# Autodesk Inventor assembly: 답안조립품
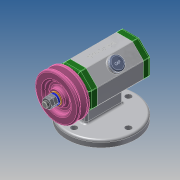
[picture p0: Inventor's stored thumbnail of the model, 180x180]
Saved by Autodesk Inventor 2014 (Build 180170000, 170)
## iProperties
Created: 2021-02
Part Number: 답안조립품
Document SubType Name: Assembly
Designer: kb542
Author: kb542
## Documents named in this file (14)
- C:\Users\kb542\Desktop\710204V1011\답안조립품.iam
- C:\Users\kb542\Desktop\710204V1011\본체.ipt
- C:\Users\kb542\Desktop\710204V1011\베어링 15 x 32 x 9.ipt
- C:\Users\kb542\Desktop\710204V1011\뒤커버.ipt
- C:\Users\kb542\Desktop\710204V1011\앞커버.ipt
- C:\Users\kb542\Desktop\710204V1011\오일 실 15 25 7.ipt
- C:\Users\kb542\Desktop\710204V1011\볼트 M4 x 12.ipt
- C:\Users\kb542\Desktop\710204V1011\축.ipt
- C:\Users\kb542\Desktop\710204V1011\키 3 x 3 x 12.ipt
- C:\Users\kb542\Desktop\710204V1011\V벨트풀리.ipt
- C:\Users\kb542\Desktop\710204V1011\와셔 8x17.ipt
- C:\Users\kb542\Desktop\710204V1011\스프링와셔 8.ipt
- C:\Users\kb542\Desktop\710204V1011\너트 M8.ipt
- C:\Users\kb542\Desktop\710204V1011\고무캡.ipt
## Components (2 placed, 2 different names)
1. V벨트풀리:1 — 각도:3, 각도:4
2. 고무캡:1 — 각도:3
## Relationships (2: Angle 2)
- 각도:3 [Angle]: V벨트풀리:1 ↔ 고무캡:1
- 각도:4 [Angle]: V벨트풀리:1
